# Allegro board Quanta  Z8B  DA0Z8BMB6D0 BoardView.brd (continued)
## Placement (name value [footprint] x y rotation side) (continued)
R522  0_6  [RC0603]  162.51 92.5 270 top
R523  *0_4  [RC0402]  175.56 103.32 270 bottom
R524  *short_4  [SHORT0402]  85.55 103.12 270 bottom
R525  *short_6  [SHORT0603]  179 102.94 0 bottom
R526  150/f_4  [RC0402]  12.88 102.79 270 bottom
R527  *0_8_s  [SHORT0805]  31.7 102.23 270 bottom
R528  0.002/f_2512  [RC2512]  141.99 101.72 0 bottom
R529  *iv@10k_4  [RC0402]  177.5 101.67 180 bottom
R531  *short_4  [SHORT0402]  148.67 101.49 0 bottom
R532  *short_4  [SHORT0402]  37.43 101.42 0 bottom
R533  130/f_4  [RC0402]  86.85 100.88 90 bottom
R534  *short_4  [SHORT0402]  85.7 100.81 270 bottom
R535  150/f_4  [RC0402]  12.88 100.75 90 bottom
R536  10k_4  [RC0402]  177.73 100.3 180 bottom
R537  2.2_6  [RC0603]  34.12 100.2 0 bottom
R538  *0_4  [RC0402]  175.49 100.02 180 bottom
R539  *short_4  [SHORT0402]  88.9 99.15 0 bottom
R540  1k_4  [RC0402]  85.23 99.14 0 bottom
R541  *330k_4  [RC0402]  176.76 98.62 0 bottom
R542  330k_4  [RC0402]  178.82 98.62 180 bottom
R543  150/f_4  [RC0402]  11.86 98.6 270 bottom
R544  *0_4  [RC0402]  86.65 97.96 0 bottom
R545  *short_4  [SHORT0402]  88.92 97.93 0 bottom
R546  *short_4  [SHORT0402]  86.65 96.73 180 bottom
R547  *0_4  [RC0402]  88.92 96.73 180 bottom
R548  *short_4  [SHORT0402]  179.48 96.39 0 bottom
R549  100k_4  [RC0402]  190.96 95.93 90 bottom
R550  *short_4  [SHORT0402]  88.91 95.52 0 bottom
R551  10k_4  [RC0402]  186.26 94.54 90 bottom
R552  *0_4  [RC0402]  88.91 94.32 180 bottom
R553  *short_4  [SHORT0402]  85.65 94.31 180 bottom
R554  10m_4  [RC0402]  178.28 94.3 90 bottom
R555  10k_4  [RC0402]  183.3 94.27 90 bottom
R556  10k_4  [RC0402]  184.86 94.25 90 bottom
R557  *short_4  [SHORT0402]  88.91 93.13 0 bottom
R558  *0_4  [RC0402]  85.65 93.12 0 bottom
R559  10k_4  [RC0402]  185.4 92.5 180 bottom
R560  0_12  [RC1206]  23.07 92.35 90 bottom
R561  *short_4  [SHORT0402]  88.92 91.93 180 bottom
R562  *short_6  [SHORT0603]  185.07 90.75 180 bottom
R563  *short_4  [SHORT0402]  88.93 90.74 180 bottom
R564  1m_8  [RC0805]  27.21 90.52 180 bottom
R565  10k_4  [RC0402]  149.9 90.41 270 bottom
R566  10k_4  [RC0402]  148.77 90.39 270 bottom
R567  *short_4  [SHORT0402]  85.83 90.08 90 bottom
R568  10k_4  [RC0402]  158.02 89.94 90 bottom
R569  *short_4  [SHORT0402]  156.95 89.94 90 bottom
R570  *1k_4  [RC0402]  152.56 89.82 90 bottom
R571  *short_4  [SHORT0402]  153.63 89.69 270 bottom
R572  *1k_4  [RC0402]  154.85 89.82 90 bottom
R573  10k_4  [RC0402]  161.7 89.82 270 bottom
R574  51_4  [RC0402]  162.85 89.82 90 bottom
R575  10k_4  [RC0402]  163.99 89.82 270 bottom
R576  10k_4  [RC0402]  165.13 89.82 270 bottom
R577  *short_4  [SHORT0402]  166.28 89.82 270 bottom
R578  10k_4  [RC0402]  167.42 89.82 270 bottom
R579  1k_4  [RC0402]  170.98 89.82 90 bottom
R580  10k_4  [RC0402]  172.12 89.82 90 bottom
R581  *short_4  [SHORT0402]  173.26 89.82 90 bottom
R582  *short_4  [SHORT0402]  175.55 89.82 270 bottom
R583  *short_4  [SHORT0402]  177.88 89.72 270 bottom
R584  10k_4  [RC0402]  174.4 89.69 90 bottom
R585  10k_4  [RC0402]  168.84 89.59 90 bottom
R586  *short_4  [SHORT0402]  169.93 89.58 270 bottom
R587  *short_4  [SHORT0402]  88.91 89.46 0 bottom
R588  *short_4  [SHORT0402]  176.71 88.46 270 bottom
R589  1k_4  [RC0402]  181.56 87.22 270 bottom
R590  10k_4  [RC0402]  163.98 87.32 90 bottom
R591  *short_4  [SHORT0402]  168.02 87.3 270 bottom
R592  *short_4  [SHORT0402]  148.75 87.28 90 bottom
R593  *0_4  [RC0402]  149.89 87.28 90 bottom
R594  390_4  [RC0402]  151.04 87.28 90 bottom
R595  *short_4  [SHORT0402]  153.22 87.28 90 bottom
R596  *1k_4  [RC0402]  154.47 87.28 90 bottom
R597  *short_4  [SHORT0402]  155.51 87.28 90 bottom
R598  10k_4  [RC0402]  156.65 87.28 90 bottom
R599  ev@10k_4  [RC0402]  159.04 87.28 270 bottom
R600  10k_4  [RC0402]  160.56 87.28 270 bottom
R601  *1k_4  [RC0402]  165.13 87.28 90 bottom
R602  *short_4  [SHORT0402]  166.28 87.28 270 bottom
R603  *short_4  [SHORT0402]  170.98 87.28 270 bottom
R604  *short_4  [SHORT0402]  172.12 87.28 90 bottom
R605  *short_4  [SHORT0402]  173.26 87.28 270 bottom
R606  10k_4  [RC0402]  174.4 87.28 90 bottom
R607  *short_4  [SHORT0402]  169.13 87.25 270 bottom
R608  *iv@100k_4  [RC0402]  157.76 87.22 270 bottom
R609  *short_4  [SHORT0402]  161.72 86.98 90 bottom
R610  *short_4  [SHORT0402]  152.07 86.28 270 bottom
R611  *short_4  [SHORT0402]  160.15 85.2 90 bottom
R612  *short_4  [SHORT0402]  162.95 85.16 90 bottom
R613  *short_4  [SHORT0402]  168.07 85.15 270 bottom
R614  10k_4  [RC0402]  166.21 85.14 270 bottom
R615  *short_4  [SHORT0402]  164.03 85.13 90 bottom
R616  *short_4  [SHORT0402]  148.75 85.12 270 bottom
R617  *short_4  [SHORT0402]  155.61 85.12 90 bottom
R618  1k_4  [RC0402]  156.75 85.12 90 bottom
R619  *short_4  [SHORT0402]  157.82 85.12 90 bottom
R620  *1k_4  [RC0402]  159.04 85.12 90 bottom
R621  *short_4  [SHORT0402]  165.13 85.12 90 bottom
R622  10k_4  [RC0402]  151.03 85.1 270 bottom
R623  *short_4  [SHORT0402]  149.9 85.1 270 bottom
R624  *0_4  [RC0402]  172.82 85.04 270 bottom
R625  *short_4  [SHORT0402]  173.97 85.04 90 bottom
R626  1/f_4  [RC0402]  30.89 84.93 0 bottom
R627  *short_4  [SHORT0402]  170.1 84.68 270 bottom
R628  10k_4  [RC0402]  154.35 84.1 90 bottom
R629  1/f_4  [RC0402]  30.89 83.79 0 bottom
R630  *short_4  [SHORT0402]  157.21 83.09 270 bottom
R631  10k_4  [RC0402]  158.28 83.09 270 bottom
R632  *short_4  [SHORT0402]  159.42 83.09 270 bottom
R633  210/f_4  [RC0402]  160.56 83.09 270 bottom
R634  100/f_4  [RC0402]  161.7 83.09 90 bottom
R635  100/f_4  [RC0402]  162.96 83.08 90 bottom
R636  10k_4  [RC0402]  165.89 82.29 270 bottom
R637  *0_4  [RC0402]  154.34 81.93 90 bottom
R638  *short_4  [SHORT0402]  167.01 81.91 90 bottom
R639  1k_4  [RC0402]  172.65 81.86 270 bottom
R640  100/f_4  [RC0402]  164.21 80.94 90 bottom
R641  *short_4  [SHORT0402]  163.01 80.71 90 bottom
R642  210/f_4  [RC0402]  165.33 80.26 270 bottom
R643  1/f_4  [RC0402]  30.31 79.94 0 bottom
R644  1k_4  [RC0402]  149.11 79.69 270 bottom
R645  15_4  [RC0402]  145.42 79.67 90 bottom
R646  15_4  [RC0402]  142.83 79.67 90 bottom
R647  15_4  [RC0402]  144.1 79.67 90 bottom
R648  15_4  [RC0402]  146.59 79.66 90 bottom
R649  15_4  [RC0402]  147.86 79.66 270 bottom
R650  1/f_4  [RC0402]  30.31 78.67 0 bottom
R651  1/f_4  [RC0402]  30.31 77.38 0 bottom
R652  *short_6  [SHORT0603]  150.73 77.18 90 bottom
R653  1/f_4  [RC0402]  30.31 76.11 0 bottom
R654  1/f_4  [RC0402]  30.33 72.33 0 bottom
R655  1/f_4  [RC0402]  30.33 71.06 0 bottom
R656  *short_4  [SHORT0402]  181.72 68.81 270 bottom
R657  1k_4  [RC0402]  144.33 67.22 90 bottom
R658  15_4  [RC0402]  145.6 67.22 270 bottom
R659  15_4  [RC0402]  146.87 67.22 270 bottom
R660  15_4  [RC0402]  148.14 67.22 270 bottom
R661  15_4  [RC0402]  149.41 67.22 270 bottom
R662  *kbl@0_4  [RC0402]  151.97 66.57 270 bottom
R663  15_4  [RC0402]  145.26 65.21 0 bottom
R664  *kbl@10k_4  [RC0402]  155.63 64.89 180 bottom
R665  *short_4  [SHORT0402]  186.56 63.66 90 bottom
R666  *0_6  [RC0603]  169.59 62.93 90 bottom
R667  *short_4  [SHORT0402]  181.91 62.8 90 bottom
R668  *short_4  [SHORT0402]  183.05 62.8 90 bottom
R669  *short_4  [SHORT0402]  184.19 62.8 90 bottom
R670  *short_4  [SHORT0402]  185.34 62.8 90 bottom
R671  *0_4  [RC0402]  171.87 62.68 270 bottom
R672  *0_4  [RC0402]  173.14 62.68 270 bottom
R673  0_4  [RC0402]  177.08 62.68 270 bottom
R674  470_4  [RC0402]  15.01 56.84 0 bottom
R675  *120/f_4  [RC0402]  13.49 56.2 270 bottom
R676  470_4  [RC0402]  15.01 55.57 0 bottom
R677  4.7k_4  [RC0402]  155.11 53.87 90 bottom
R678  4.7k_4  [RC0402]  155.09 51.58 270 bottom
R679  *0_4  [RC0402]  186.35 48.96 180 bottom
R680  4.7k_4  [RC0402]  188.64 48.96 0 bottom
R681  100k_4  [RC0402]  174.29 48.45 0 bottom
R682  *short_4  [SHORT0402]  163.45 47.9 90 bottom
R683  *0_4  [RC0402]  165.19 47.36 90 bottom
R684  *0_4  [RC0402]  166.34 47.36 90 bottom
R685  *short_8  [SHORT0805]  168.8 48.52 180 bottom
R686  *short_4  [SHORT0402]  180.89 47.06 90 bottom
R687  *short_4  [SHORT0402]  182.03 47.06 90 bottom
R688  4.7k_4  [RC0402]  183.58 47.06 90 bottom
R689  *0_4  [RC0402]  186.37 45.21 0 bottom
R690  *short_6  [SHORT0603]  33.24 34.71 0 bottom
R691  4.7k_4  [RC0402]  25.81 34.61 270 bottom
R692  *0_4  [RC0402]  29.24 34.61 270 bottom
R693  *short_4  [SHORT0402]  30.25 34.61 90 bottom
R694  10k_4  [RC0402]  19.28 33.57 0 bottom
R695  100k_4  [RC0402]  21.77 30.17 270 bottom
R696  *10k/f_4  [RC0402]  38.13 26.49 90 bottom
R697  *29.4k/f_4  [RC0402]  38.13 24.2 270 bottom
R698  *short_4  [SHORT0402]  29.62 19.25 90 bottom
R699  90.9_4  [RC0402]  38.38 19.12 270 bottom
R700  90.9_4  [RC0402]  35.97 18.99 270 bottom
R701  90.9_4  [RC0402]  40.79 18.99 270 bottom
R702  90.9_4  [RC0402]  19.2 18.23 270 bottom
R703  90.9_4  [RC0402]  20.47 18.23 270 bottom
R704  90.9_4  [RC0402]  21.74 18.23 270 bottom
R705  90.9_4  [RC0402]  23.4 18.23 270 bottom
R706  90.9_4  [RC0402]  26.32 18.23 270 bottom
R707  *1k_4  [RC0402]  28.5 18.13 90 bottom
R708  *100k_4  [RC0402]  31.5 17.72 180 bottom
R709  *short_6  [SHORT0603]  38.64 14.8 180 bottom
R710  *short_4  [SHORT0402]  36.86 13.53 180 bottom
R711  *short_4  [SHORT0402]  36.86 12.52 180 bottom
R712  *short_4  [SHORT0402]  170.87 11.99 180 bottom
R713  10k_4  [RC0402]  173.15 11.99 0 bottom
R714  *0_4  [RC0402]  175.41 12.08 0 bottom
R715  *short_4  [SHORT0402]  170.87 10.59 180 bottom
R716  10k_4  [RC0402]  173.15 10.59 0 bottom
R717  *0_4  [RC0402]  174.68 9.67 270 bottom
R718  *1m_4  [RC0402]  66.96 9.59 270 bottom
R719  *1m_4  [RC0402]  68.23 9.59 270 bottom
R720  *short_4  [SHORT0402]  173.15 9.39 0 bottom
R721  *1m_4  [RC0402]  63.91 8.83 270 bottom
R722  *1m_4  [RC0402]  65.18 8.83 270 bottom
R723  680/f_4  [RC0402]  66.96 7.31 90 bottom
R724  2k/f_4  [RC0402]  68.23 7.31 90 bottom
R725  680/f_4  [RC0402]  63.91 6.67 90 bottom
R726  2k/f_4  [RC0402]  65.18 6.67 90 bottom
R727  *short_4  [SHORT0402]  103.36 5.15 0 bottom
R728  2.2k_4  [RC0402]  24.29 111.83 90 top
R729  2.2k_4  [RC0402]  18.55 113.36 90 top
R730  2.2k_4  [RC0402]  22 109.67 90 top
R731  2.2k_4  [RC0402]  20.98 109.67 90 top
R732  ev@10k_4  [RC0402]  161.07 179.27 180 top
R733  ev@10k_4  [RC0402]  168.3 148.79 90 bottom
R734  *short_4  [SHORT0402]  135.16 116.66 180 bottom
R735  *short_4  [SHORT0402]  135.16 117.67 180 bottom
R736  *short_4  [SHORT0402]  135.16 115.64 180 bottom
R737  *short_4  [SHORT0402]  135.16 114.62 180 bottom
R738  *short_4  [SHORT0402]  135.16 112.59 180 bottom
R739  *short_4  [SHORT0402]  135.16 113.61 180 bottom
R740  *10k_4  [RC0402]  183.01 173.07 270 top
R741  *1k_4  [RC0402]  176.74 175.94 180 top
R742  *1k_4  [RC0402]  173.18 172.87 90 top
R743  ev@0_4  [RC0402]  171.23 162.43 90 bottom
R744  *short_4  [SHORT0402]  149.41 122.87 270 bottom
R745  *short_4  [SHORT0402]  148.4 122.87 270 bottom
R746  *short_4  [SHORT0402]  175.7 10.44 270 bottom
RP1  10k_10p8r_6  [10P8R]  167.93 86.14 90 top
RP2  *10k_10p8r  [10P8R]  177.57 20.01 180 top
RP7  10k_10p8r_6  [10P8R]  182.3 100.53 0 bottom
RV1  *ega_4  [RC0402]  17.05 39.06 180 bottom
RV2  *ega_4  [RC0402]  17.05 37.92 180 bottom
RV3  *ega_4  [RC0402]  17.07 36.75 180 bottom
RV4  *ega_4  [RC0402]  17.07 35.6 180 bottom
RV5  *ega_4  [RC0402]  17.05 34.38 180 bottom
RV6  *ega_4  [RC0402]  17.05 33.24 180 bottom
SW1  *power switch  [SW-TC901-AA1G-A160T-6P]  161.32 68.9 270 top
T1  *pad  [TP2650]  25.63 25.61 0 top
T2  *pad  [TP2650]  25.74 24.23 0 top
TP1  *  [TP2650]  106.76 189.48 0 top
TP2  *  [TP2650]  108.06 189.45 0 top
TP3  *  [TP2650]  108.56 188.11 0 top
TP4  *  [TP2650]  107.09 187.7 0 top
TP5  *  [TP2050]  146.44 169.97 90 top
TP6  *  [TP2675]  150.14 166.31 90 top
TP7  *  [TP2675]  151.16 164.68 90 top
TP8  *  [TP2050]  149.75 163.36 90 top
TP9  *  [TP2650]  134.24 161.51 90 top
TP10  *  [TP2650]  139.65 158.78 90 top
TP11  *  [TP2650]  187.58 150.13 0 top
TP12  *  [TP2675]  118.47 126 270 top
TP13  *  [TP2650]  97.3 124.09 0 top
TP14  *  [TP2675]  118.44 124.05 270 top
TP15  *  [TP2675]  94.57 122.14 270 top
TP16  *  [TP2675]  94.26 120.21 270 top
TP17  *  [TP2650]  98.78 118.43 0 top
TP18  *  [TP2650]  97.01 117.42 0 top
TP19  *  [TP2650]  171.73 115.51 0 top
TP20  *  [TP2650]  93.23 114.57 0 top
TP21  *  [TP2650]  170.72 113.69 0 top
TP22  *  [TP2675]  93.2 112.87 90 top
TP23  *  [TP2675]  91.09 112.85 90 top
TP24  *  [TP2675]  94.85 111.19 90 top
TP25  *  [TP2650]  169.22 110.84 0 top
TP26  *  [TP2675]  90.99 110.86 90 top
TP27  *  [TP2650]  131.22 110.76 0 top
TP28  *  [TP2675]  92.97 110.56 90 top
TP29  *  [TP2675]  90.86 108.91 270 top
TP30  *  [TP2650]  87.18 108.09 0 top
TP31  *  [TP2650]  85.81 108.05 0 top
TP32  *  [TP2650]  24.01 102.61 180 top
TP33  *  [TP2650]  22.03 102.35 90 top
TP34  *  [TP2650]  86.34 102.05 0 top
TP35  *  [TP2675]  171.23 101.8 0 top
TP36  *  [TP2650]  22 100.65 180 top
TP37  *  [TP2650]  85.17 100.58 0 top
TP38  *  [TP2650]  8.04 100.48 0 top
TP39  *  [TP2650]  84.42 98.77 0 top
TP40  *  [TP2675]  147.07 98.44 0 top
TP41  *  [TP2650]  85.75 98.42 0 top
TP42  *  [TP2675]  149.7 98.32 0 top
TP43  *  [TP2675]  147.07 96.49 0 top
TP44  *  [TP2675]  149.76 96.41 0 top
TP45  *  [TP2675]  159.67 96.54 0 top
TP46  *  [TP2675]  162.69 95.6 0 top
TP47  *  [TP2675]  165.56 95.29 0 top
TP48  *  [TP2675]  155.73 94.68 0 top
TP49  *  [TP2675]  160.79 94.96 0 top
TP50  *  [TP2675]  159.76 98.56 0 top
TP51  *  [TP2675]  170.79 92.75 0 top
TP52  *  [TP2675]  158.68 93.8 0 top
TP53  *  [TP2675]  154.78 91.49 0 top
TP54  *  [TP2675]  103 90.37 270 top
TP55  *  [TP2675]  170.16 89.99 0 top
TP56  *  [TP2675]  106.38 89.5 270 top
TP57  *  [TP2675]  162.98 87.02 0 top
TP58  *  [TP2650]  161.73 85.98 0 top
TP59  *  [TP2675]  185.45 84.75 0 top
TP60  *  [TP2650]  159.03 83.37 0 top
TP61  *  [TP2675]  179.9 82.51 0 top
TP62  *  [TP2650]  126.09 82.03 0 top
TP63  *  [TP2675]  180.04 80.49 0 top
TP64  *  [TP2650]  60.63 76.24 0 top
TP65  *  [TP2650]  166.32 70.79 0 top
TP66  *  [TP2650]  166.27 69.28 0 top
TP67  *  [TP2650]  156.49 67.13 0 top
TP68  *  [TP2650]  77.39 66.32 0 top
TP69  *  [TP2650]  178.95 65.47 0 top
TP70  *  [TP2650]  186 57.11 0 top
TP71  *  [TP2650]  140.21 54.27 0 top
TP72  *  [TP2650]  166.65 45.23 0 top
TP73  *  [TP2650]  34.26 33.07 90 top
TP74  *  [TP2650]  164.55 17.87 0 top
TP75  *  [TP2650]  118.01 11.25 0 top
TP76  *  [TP2650]  48.19 7.69 0 top
TP77  *  [TP2650]  177.68 174.03 180 bottom
TP78  *  [TP2650]  136.83 173.12 270 bottom
TP79  *  [TP2675]  163.5 149.04 270 bottom
TP80  *  [TP2675]  165.23 147.74 270 bottom
TP81  *  [TP2675]  150.63 141.57 270 bottom
TP82  *  [TP2675]  154.54 141.12 270 bottom
TP83  *  [TP2650]  93.63 123.03 180 bottom
TP84  *  [TP2650]  93.7 121.74 180 bottom
TP85  *  [TP2650]  148.64 120.44 180 bottom
TP86  *  [TP2650]  147.38 120.37 180 bottom
TP87  *  [TP2650]  170.18 117.59 180 bottom
TP88  *  [TP2650]  86.01 114.12 180 bottom
TP89  *  [TP2650]  84.71 114.06 180 bottom
TP90  *  [TP2650]  89.44 113.73 180 bottom
TP91  *  [TP2650]  85.32 111.83 180 bottom
TP92  *  [TP2650]  86.67 111.75 180 bottom
TP93  *  [TP2650]  87.94 109.47 180 bottom
TP94  *  [TP2650]  89.41 109.42 180 bottom
TP95  *  [TP2650]  85.17 109.04 180 bottom
TP96  *  [TP2650]  85.48 106.98 180 bottom
TP97  *  [TP2650]  87.2 106.5 180 bottom
TP98  *  [TP2675]  175.73 106.11 180 bottom
TP99  *  [TP2650]  86.08 105.86 180 bottom
TP100  *  [TP2650]  87.33 105.02 180 bottom
TP101  *  [TP2650]  139.27 105.02 180 bottom
TP102  *  [TP2050]  174.6 103.27 180 bottom
TP103  *  [TP2675]  179.73 101.85 180 bottom
TP104  *  [TP2650]  39.45 101.57 180 bottom
TP105  *  [TP2650]  87.07 99.07 180 bottom
TP106  *  [TP2675]  175.34 98.72 180 bottom
TP107  *  [TP2675]  149.05 98.37 180 bottom
TP108  *  [TP2675]  147.12 98.34 270 bottom
TP109  *  [TP2650]  83.77 98.19 180 bottom
TP110  *  [TP2650]  85.06 97.95 180 bottom
TP111  *  [TP2675]  146.59 96.44 270 bottom
TP112  *  [TP2675]  148.77 96.44 180 bottom
TP113  *  [TP2650]  85.07 95.54 180 bottom
TP114  *  [TP2650]  86.34 95.53 180 bottom
TP115  *  [TP2675]  149.03 94.51 0 bottom
TP116  *  [TP2675]  147.1 94.43 0 bottom
TP117  *  [TP2650]  87.25 93.77 180 bottom
TP118  *  [TP2675]  145.6 93.16 180 bottom
TP119  *  [TP2675]  147.38 92.3 180 bottom
TP120  *  [TP2650]  84.58 91.97 180 bottom
TP121  *  [TP2650]  87.2 91.89 180 bottom
TP122  *  [TP2650]  85.91 91.88 180 bottom
TP123  *  [TP2675]  175.47 91.36 90 bottom
TP124  *  [TP2650]  153.6 91.31 180 bottom
TP125  *  [TP2650]  155.38 91.26 180 bottom
TP126  *  [TP2650]  87.13 90.6 180 bottom
TP127  *  [TP2675]  179.38 90.21 180 bottom
TP128  *  [TP2650]  155.97 89.24 180 bottom
TP129  *  [TP2650]  87.17 89.2 180 bottom
TP130  *  [TP2675]  177.86 88.13 180 bottom
TP131  *  [TP2650]  170.05 87.91 180 bottom
TP132  *  [TP2650]  152.14 87.8 180 bottom
TP133  *  [TP2675]  175.5 87.35 90 bottom
TP134  *  [TP2650]  167.19 85.85 180 bottom
TP135  *  [TP2650]  154.54 85.8 180 bottom
TP136  *  [TP2650]  153.06 85.49 180 bottom
TP137  *  [TP2650]  161.24 85 180 bottom
TP138  *  [TP2650]  167.19 84.58 180 bottom
TP139  *  [TP2650]  152.15 84.53 180 bottom
TP140  *  [TP2675]  171.68 83.89 90 bottom
TP141  *  [TP2650]  165.13 83.69 180 bottom
TP142  *  [TP2650]  168.12 83.67 180 bottom
TP143  *  [TP2675]  173.64 83.48 90 bottom
TP144  *  [TP2650]  163.89 83.43 180 bottom
TP145  *  [TP2650]  166.88 83.34 180 bottom
TP146  *  [TP2650]  156.12 83.31 180 bottom
TP147  *  [TP2650]  170.1 83.25 180 bottom
TP148  *  [TP2650]  168.92 82.65 180 bottom
TP149  *  [TP2650]  164.7 82.42 180 bottom
TP150  *  [TP2650]  156.52 81.53 180 bottom
TP151  *  [TP2650]  159.43 81.38 180 bottom
TP152  *  [TP2650]  169.17 81.3 180 bottom
TP153  *  [TP2650]  171.73 80.61 180 bottom
TP154  *  [TP2650]  161.92 80.32 180 bottom
TP155  *  [TP2650]  54.54 77.31 180 bottom
TP156  *  [TP2650]  170.63 63.16 180 bottom
TP157  *  [TP2650]  16.62 61.26 180 bottom
TP158  *  [TP2650]  153.66 56.12 180 bottom
TP159  *  [TP2650]  46.26 55.47 180 bottom
TP160  *  [TP2650]  155.12 55.47 180 bottom
TP161  *  [TP2650]  154.15 52.24 180 bottom
TP162  *  [TP2650]  154.13 50.89 180 bottom
TP163  *  [TP2650]  165.2 49.06 180 bottom
TP164  *  [TP2650]  145.67 47.21 180 bottom
TP165  *pad  [TP2650]  28.86 16.45 270 bottom
TP166  *pad  [TP2650]  34.32 10.53 270 bottom
TP167  *  [TP2650]  170.34 9.42 180 bottom
TP168  *  [TP2650]  171.68 9.42 180 bottom
TP169  *pad  [TP2650]  30.08 9.31 270 bottom
TP170  *pad  [TP2650]  31.58 9.31 270 bottom
TP171  *pad  [TP2650]  32.95 9.26 270 bottom
TP172  *pad  [TP2650]  34.35 9.24 270 bottom
TP173  *pad  [TP2650]  27.82 8.88 270 bottom
TP174  *pad  [TP2650]  30.13 8.04 270 bottom
TP175  *pad  [TP2650]  31.4 8.04 270 bottom
TP176  *  [TP2650]  74.83 6.39 180 bottom
TP177  *  [TP2675]  146.74 65.25 0 top
TP178  *  [TP2675]  144.96 81.32 180 bottom
TP179  *  [TP2675]  145.37 77.69 0 top
TP180  *  [TP2675]  144.86 65.6 0 top
TP181  *  [TP2675]  182.5 87.95 180 bottom
U1  *g780p81u  [MSOP8-4_9-65]  166.78 177.74 90 top
U2  g5243at11u  [SOT23-2_8-95-6P]  109.07 174.36 270 top
U3  *74aup1g07gw  [SOT353-1-2_125-65-5P]  179.94 170.62 0 top
U5  74lvc1g07gw  [SOT353-2_1-65-5P-1_1H]  84.41 103.12 270 top
U6  *rclamp0524p  [SLP10-2_5X1-5-10P]  9.76 100.93 90 top
U7  rtl8111gs-cg  [QFN32-4X4-4-33P-0_9H]  27.92 98.34 0 top
U8  tc7sh08fu  [SSOP5-P-A-TOSHIBA-B]  183.4 82.47 90 top
U9  *cm1293a-04so  [TSOP6-2_8-95]  30.99 82.03 180 top
U10  *cm1293a-04so  [TSOP6-2_8-95]  32.26 76.24 270 top
U11  tpm@npct650aa0wx_tssop28  [TSSOP28-6_4-65-SLB9635TT]  182.42 71.06 180 top
U12  *74ahc1g09gw  [SOT353-1-2_125-65-5P]  77.04 70.22 270 top
U13  it8587e/fx  [LQFP128-16X16-4-1_6H]  175.43 54.93 270 top
U15  alc283  [QFN48-6X6-4-49P-ALC280]  30 29.03 180 top
U16  *gs@lis3dhtr  [SENSOR-3X3-5-16P-SMT]  113.18 12.9 0 top
U17  d-mic  [MIC-MP45DT02TR-6P]  104.5 3.35 180 top
U18  *ev@sn74ahc1g32dckr  [SSOP5-P-A-TOSHIBA-B]  169.24 162.43 90 bottom
U19  ev@n15s  [BGA595-NVIDIA-N13P-GV2-S-A2]  146.69 158.34 180 bottom
U20  evg@mc74vhc1g08dft2g  [SSOP5-P-A-TOSHIBA-B]  168.71 153 270 bottom
U21  *ev@mc74vhc1g08dft2g  [SSOP5-P-A-TOSHIBA-B]  166 152.98 270 bottom
U22  m74vhc1gt125df2g  [SSOP5-P-A-TOSHIBA-B]  14.38 107.64 270 bottom
U23  *rclamp0524p  [SLP10-2_5X1-5-10P]  9.7 106.72 90 bottom
U24  lpt_pch_m_eds/bga  [BGA695-INTEL-LYNX-POINT]  162.2 104.45 270 bottom
U25  m74vhc1gt125df2g  [SSOP5-P-A-TOSHIBA-B]  14.76 103.45 270 bottom
U26  g991p11u  [SOIC8-6-1_27]  58.7 101.87 270 bottom
U27  hsw_rpga_eds_pga  [PZ94726-3641-41H-SOCKET]  111.9 99.69 180 bottom
U28  tc7sh08fu  [SSOP5-P-A-TOSHIBA-B]  192.18 99.51 0 bottom
U29  ns692417  [TRF-9_4-1_27-24P]  23.37 78.02 270 bottom
U30  w25q64fvssiq  [SOIC8-7_9-1_27]  147.22 73.48 180 bottom
U31  *g923-330t1uf  [SOT23-5]  40.54 25.47 0 bottom
U32  qfn24-3.3v  [QFN24-4X4-5-25P-1H]  30.89 12.69 180 bottom
U33  g524b2t11u  [SOT23-5]  23.4 43.76 180 top
VC1  *tvm0g5r5m261r_4  [CC0402]  27.08 43 270 top
VC2  *tvm0g5r5m261r_4  [CC0402]  17.94 45.15 90 bottom
VRAM1  ev@vram _ddr3_hynix_256mx16  [FBGA96-AMD-23EY4187MA11]  121.15 168.34 0 top
VRAM2  ev@vram _ddr3_hynix_256mx16  [FBGA96-AMD-23EY4187MA11]  121.15 148.05 180 top
VRAM3  ev@vram _ddr3_hynix_256mx16  [FBGA96-AMD-23EY4187MA11]  121.15 168.34 180 bottom
VRAM4  ev@vram _ddr3_hynix_256mx16  [FBGA96-AMD-23EY4187MA11]  121.15 148.05 0 bottom
Y1  25mhz +-30ppm  [XTL-3_2X2_5-2_2X1_7]  21.01 97.61 90 top
Y2  ev@27mhz  [XTL-3_2X2_5-2_2X1_6]  153.22 176.9 180 bottom
Y3  25mhz +-30ppm  [XTL-3_2X2_5-2_2X1_7]  157.51 120.43 0 bottom
Y4  32.768khz  [XTL-3_2X1_5-2_5-0_8H]  179.91 93.67 270 bottom

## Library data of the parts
BT1 = ML1220-SMT
C1 C2 C4-C10 C12-C15 C17-C25 C27 C29 C34 C35 C40-C42 C47-C49 C51 C53 C55 C58 C64 C70-C75 C80 C82-C98 C103-C114 C116 C120-C127 C129-C137 C140-C157 C160-C169 C175 C177-C183 C189 C190 C196 C198 C204 C211 C213 C215-C230 C232 C235-C240 C242-C245 C247-C250 C257 C259 C260 C263 C265-C267 C270-C274 C278 C284 C285 C288-C292 C296 C300-C338 C340-C357 C359-C361 C363-C365 C367 C369-C376 C379 C387 C389 C391-C405 C407 C409-C427 C429 C430 C432 C433 C435-C438 C445-C447 C449 C452 C457-C459 C462 C463 C469-C475 C481-C485 C487 C488 C494-C499 C501-C504 C506-C508 C510-C515 C517-C523 C525-C534 C536 C538-C542 C544 C545 C547-C549 C551 C553-C558 C560-C568 C570 C716-C754 PC13 PC20 PC21 PC23-PC28 PC33 PC49 PC52 PC59 PC61 PC62 PC68-PC70 PC72 PC77 PC78 PC80 PC86-PC94 PC98 PC101-PC105 PC112 PC113 PC115 PC116 PC119 PC121-PC124 PC126 PC130 PC131 PC136 PC139 PC140 PC142 PC145-PC148 PC154-PC158 PC161 PC163 PC166 PC168 VC1 VC2 = CC0402
C3 C26 C28 C30 C31 C33 C36-C39 C43-C46 C50 C52 C54 C56 C57 C59-C63 C65-C69 C76-C79 C81 C99-C102 C138 C205 C212 C214 C233 C234 C241 C246 C252-C255 C258 C261 C262 C264 C268 C269 C275 C276 C279-C282 C286 C293-C295 C297 C298 C339 C366 C368 C377 C378 C380 C382-C386 C406 C434 C444 C448 C450 C460 C461 C509 C516 C524 C535 C537 C546 C550 C552 C559 C715 PC1-PC12 PC15 PC16 PC18 PC22 PC31 PC32 PC34 PC35 PC37 PC38 PC40 PC41 PC43-PC48 PC50 PC53 PC54 PC56-PC58 PC60 PC64 PC65 PC67 PC71 PC76 PC79 PC84 PC85 PC95-PC97 PC99 PC100 PC106-PC108 PC114 PC120 PC125 PC127 PC135 PC138 PC141 PC149 PC151 PC152 PC160 PC167 PC169 PC170 = CC0603
C11 C16 C32 C115 C117 C118 C128 C139 C158 C159 C170-C174 C176 C184-C188 C191-C195 C197 C199-C203 C206-C210 C231 C251 C256 C277 C299 C362 C388 C390 C408 C431 C439-C443 C451 C453-C456 C464-C468 C476-C480 C486 C489-C493 C543 PC14 PC17 PC19 PC30 PC36 PC51 PC63 PC73 PC74 PC82 PC83 PC109 PC110 PC117 PC128 PC129 PC132 PC137 PC143 PC144 PC150 PC159 PC164 PC165 = CC0805
C287 C358 C428 C569 = CC3528
C381 L6 L16 L19 L22 L23 L29 L30 L32 L33 PR22 PR48 PR49 PR51 PR53 PR61 PR64-PR66 PR73 PR79 PR82 PR83 PR88 PR94 PR105 PR126 PR144 PR152 PR155 PR160 PR168 PR175 PR177 PR183 PR190 PR209 PR210 PR213-PR216 R5 R72 R136 R139 R151 R181 R225 R263 R267-R269 R272 R285 R295 R313 R322 R337 R365 R522 R537 R666 = RC0603
C500 = CC1808
C505 = ECAP6D3S
CN1 = SDCARD-5-251301001000-6-11P-SMT
CN2 = GS12401-1011-40P-R-NH-SMT
CN3 = HS8803F-3P-L
CN4 CN8 = 50503-0040N-V01-4P-L
CN5 = DSUB-070546FR015S265ZR-15P-V
CN6 = SATA-C185Q2-11311-L-13P-R
CN7 = RJ45-C100JH-10805-L-8P
CN9 = HDMI-2HE1638-000111F-19P
CN10 = MIPCI-800055FB052GX00PL-52P-SMT
CN11 = HDD-193204-1-22P-R
CN12 = USB-C19083-90905-L-9P
CN13 = 51553-01041-001-10P-L
CN14 = 88502-260N-26P-L-SMT
CN15 = AUDIO-313301-1-6P
CN16 = 196479-06041-3-6P-L
CN17 = 50501-02401-001-24P-L
CN18 = 196297-06021-3-6P-L
CN19 = 50273-0040L-001-4P-L
CP1-CP6 = 8P4R
D1 D3 D4 D6-D10 D12-D15 D18 D23 PD3 PD4 PD7 = DSM
D2 = CC1206
D5 D17 D19 D24 L1-L4 L9 L10 L12 L17 L18 L25-L27 PR3 PR4 PR6 PR8 PR10-PR12 PR14 PR15 PR17 PR25-PR28 PR30 PR31 PR33-PR36 PR38-PR42 PR44 PR47 PR50 PR52 PR54 PR55 PR57 PR58 PR67 PR70-PR72 PR74-PR76 PR80 PR81 PR84-PR87 PR89-PR93 PR95-PR103 PR106-PR114 PR118-PR121 PR127-PR130 PR132-PR134 PR137 PR140-PR143 PR145 PR149 PR150 PR153 PR154 PR156 PR157 PR159 PR161-PR163 PR165 PR169 PR170 PR172-PR174 PR176 PR178 PR179 PR182 PR184 PR189 PR191-PR193 PR195-PR197 PR199 PR201-PR203 PR205 PR207 PR208 PR211 PR212 R1-R4 R7 R9-R16 R18-R25 R27 R29 R30 R32-R43 R45-R49 R51 R52 R56-R58 R60 R63 R65 R68 R69 R71 R77 R79-R86 R89-R94 R96 R100 R102 R104 R106 R107 R109 R111-R113 R115 R119-R122 R124-R126 R130 R131 R133 R135 R137 R138 R140 R146 R147 R153-R162 R164 R166-R180 R182-R189 R193 R194 R196-R199 R201 R203-R210 R214 R216 R217 R219-R224 R226 R227 R229-R232 R235 R238 R240-R244 R246 R247 R249-R255 R258-R262 R264-R266 R270 R271 R275 R276 R278 R279 R281-R284 R287-R291 R293 R294 R296-R298 R300 R302-R308 R310 R311 R314-R321 R323-R326 R329-R334 R338 R340-R343 R345 R346 R348 R351-R353 R355 R357 R358 R360-R362 R366-R370 R376-R378 R383-R411 R413-R415 R418-R424 R426-R433 R435-R454 R457 R459-R461 R463-R467 R469 R471-R476 R479 R480 R483 R490 R492 R494-R498 R501 R503 R505-R510 R513-R515 R517-R521 R523 R526 R529 R533 R535 R536 R538 R540-R544 R547 R549 R551 R552 R554-R556 R558 R559 R565 R566 R568 R570 R572-R576 R578-R580 R584 R585 R589 R590 R593 R594 R596 R598-R601 R606 R608 R614 R618 R620 R622 R624 R626 R628 R629 R631 R633-R637 R639 R640 R642-R651 R653-R655 R657-R664 R671-R681 R683 R684 R688 R689 R691 R692 R694-R697 R699-R708 R713 R714 R716-R719 R721-R726 R728-R733 R740-R743 RV1-RV6 = RC0402
D11 = DSMV
D16 D20 = D-SOD523-1_2X0_8-0_65H
D21 = CC1812
D22 = SOT323_213-2_1-1_3-2N7002W
HOLE1 = HG-TC394BC217D118P2
HOLE2 = HG-TR299X327BC315D118P2
HOLE3 = HG-TC394BC315D118P2
HOLE4 HOLE6 = H-TC236I140BC266D140P2
HOLE5 = H-TC276BC217D118P2
HOLE7 HOLE14 HOLE15 = H-TC315I158BC197D158P2
HOLE8 = HG-C315D189P2
HOLE9 = H-Z8B-1
HOLE10 HOLE11 = SPAD-C236NSNP
HOLE12 HOLE21 HOLE22 = HG-TC276BC315D118P2
HOLE13 = H-C102D102N
HOLE16 = H-ZQ0-1
HOLE17 = H-TC217BC197D140P2
HOLE18 = H-TS315I118BC315D118P2
HOLE19 = O-Z8B-1
HOLE20 HOLE24 = H-C177D177N
HOLE25 = HG-C276D118P2
J2 = SOLDERJUMPER-2
JDIM1 = DDR-DDRSK-20401-TP8D-204P-LDV
JDIM2 = DDR-DS2SK-20401-TP4B-STD-204P
L5 L7 L8 L28 PL5 PL10 PL14 PL15 PR60 PR62 PR63 PR104 PR146-PR148 PR194 PR198 PR204 PR217 PR218 R8 R150 R245 R462 R468 R489 R564 = RC0805
L24 = L3_2X2_5-3_2
LED1 LED2 = LED19-123-Y2ST1D-C30-2T-4P
PC29 PC39 PC42 PC55 PC66 PC75 PC111 PC134 = ECAP6_3X6_1-7_2
PC118 PC133 PC153 PC162 = CC7343
PD1 = POWER-6_5-1_84-3P
PD2 = D-DO-214AC
PD5 PD6 PQ18 PQ29 PQ30 PQ51 Q6 Q9 Q11 Q17 Q28 Q30 Q48 Q50 Q51 = UMT_213-3-1_3
PJ1 = 20288-04XX-4P-L
PJ2 = BAT-C144PL-K08A9-L-8P-L
PL1-PL4 PL7 PL11 PL13 = CHOKE-PCMC063T-3R3MN-SMT
PL6 PL12 = CHOKE-PCMC063T-R82MN-4P-SMT
PL8 PL9 = CHOKE-ETQP4LR36AFM
PQ1 PQ2 PQ36-PQ39 = SO-8FL-5P-OA
PQ3 = IMD
PQ4 PQ8 PQ9 PQ16 PQ17 PQ19-PQ21 PQ27 PQ28 PQ31-PQ35 PQ40 PQ42 PQ44-PQ50 PQ52 PQ53 Q1 Q2 Q4 Q5 Q7 Q10 Q12-Q16 Q18 Q20 Q22-Q27 Q29 Q32-Q43 Q45-Q47 Q49 Q52-Q55 Q57 Q59 Q60 = SOT23_213-3_3-2
PQ5 PQ7 PQ10-PQ15 PQ22-PQ26 PQ43 = WDFN5-3_05X3_05-65
PQ6 Q3 Q8 Q21 Q44 Q56 Q58 = SC70-2_1-65-6P
PQ41 = POWER-5X6-1_27-7P
PR1 PR20 = RC3216
PR2 PR5 PR7 PR18 PR19 PR21 PR23 PR24 PR32 PR37 PR45 PR46 PR68 PR77 PR78 PR115-PR117 PR122 PR123 PR125 PR131 PR135 PR136 PR139 PR164 PR166 PR167 PR171 PR180 PR181 PR185-PR188 PR200 PR206 R26 R28 R31 R44 R50 R59 R66 R87 R88 R97 R103 R110 R118 R123 R132 R141 R148 R152 R163 R165 R191 R192 R195 R200 R202 R211-R213 R215 R218 R228 R234 R239 R256 R257 R273 R274 R277 R280 R299 R301 R328 R336 R339 R344 R347 R349 R350 R354 R356 R359 R363 R364 R375 R379-R382 R412 R425 R434 R455 R456 R458 R470 R478 R481 R484-R487 R491 R499 R500 R502 R504 R511 R516 R524 R531 R532 R534 R539 R545 R546 R548 R550 R553 R557 R561 R563 R567 R569 R571 R577 R581-R583 R586-R588 R591 R592 R595 R597 R602-R605 R607 R609-R613 R615-R617 R619 R621 R623 R625 R627 R630 R632 R638 R641 R656 R665 R667-R670 R682 R686 R687 R693 R698 R710-R712 R715 R720 R727 R734-R739 R744-R746 = SHORT0402
PR9 PR16 PR29 PR43 PR56 PR59 PR69 PR138 PR151 PR158 R6 R55 R67 R70 R73 R74 R76 R78 R95 R98 R99 R108 R114 R116 R127 R129 R143 R144 R149 R286 R292 R309 R312 R335 R371-R374 R416 R417 R493 R525 R562 R652 R690 R709 = SHORT0603
PR13 R105 R117 R128 R233 R236 R237 R248 R482 R560 = RC1206
PR124 R17 R53 R54 R61 R62 R64 R75 R101 R134 R142 R190 R327 R477 R488 R512 R527 R685 = SHORT0805
PU1 = PVQFN20-3_5X3_5-5-25P
PU2 = SOT23-6-2_8-95-6P
PU3 PU5 = QFN20-3X3-4-26P
PU4 PU11 = SON10-3X3-5-16P
PU6 PU12 = SON8-4_5X3_5-5-9P-SMT
PU7 = QFN32-4X4-4-42P-1H
PU8 = QFN16-3X3-5-22P
PU9 U26 = SOIC8-6-1_27
PU10 = QFN20-3X3-4-21P-0_8H
Q19 U9 U10 = TSOP6-2_8-95
Q31 = POWER-3_3X3_3-65-5P-SMT
R145 R528 = RC2512
RP1 RP2 RP7 = 10P8R
SW1 = SW-TC901-AA1G-A160T-6P
T1 T2 TP1-TP4 TP9-TP11 TP13 TP17-TP21 TP25 TP27 TP30-TP34 TP36-TP39 TP41 TP58 TP60 TP62 TP64-TP78 TP83-TP97 TP99-TP101 TP104 TP105 TP109 TP110 TP113 TP114 TP117 TP120-TP122 TP124-TP126 TP128 TP129 TP131 TP132 TP134-TP139 TP141 TP142 TP144-TP176 = TP2650
TP5 TP8 TP102 = TP2050
TP6 TP7 TP12 TP14-TP16 TP22-TP24 TP26 TP28 TP29 TP35 TP40 TP42-TP57 TP59 TP61 TP63 TP79-TP82 TP98 TP103 TP106-TP108 TP111 TP112 TP115 TP116 TP118 TP119 TP123 TP127 TP130 TP133 TP140 TP143 TP177-TP181 = TP2675
U1 = MSOP8-4_9-65
U2 = SOT23-2_8-95-6P
U3 U12 = SOT353-1-2_125-65-5P
U5 = SOT353-2_1-65-5P-1_1H
U6 U23 = SLP10-2_5X1-5-10P
U7 = QFN32-4X4-4-33P-0_9H
U8 U18 U20-U22 U25 U28 = SSOP5-P-A-TOSHIBA-B
U11 = TSSOP28-6_4-65-SLB9635TT
U13 = LQFP128-16X16-4-1_6H
U15 = QFN48-6X6-4-49P-ALC280
U16 = SENSOR-3X3-5-16P-SMT
U17 = MIC-MP45DT02TR-6P
U19 = BGA595-NVIDIA-N13P-GV2-S-A2
U24 = BGA695-INTEL-LYNX-POINT
U27 = PZ94726-3641-41H-SOCKET
U29 = TRF-9_4-1_27-24P
U30 = SOIC8-7_9-1_27
U31 U33 = SOT23-5
U32 = QFN24-4X4-5-25P-1H
VRAM1-VRAM4 = FBGA96-AMD-23EY4187MA11
Y1 Y3 = XTL-3_2X2_5-2_2X1_7
Y2 = XTL-3_2X2_5-2_2X1_6
Y4 = XTL-3_2X1_5-2_5-0_8H

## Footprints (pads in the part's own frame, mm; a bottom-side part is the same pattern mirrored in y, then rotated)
8P4R
  rect 0.406x1.092 smd: 1(-1.194,-0.8) 2(-1.194,0.8) 3(-0.406,-0.8) 4(-0.406,0.8) 5(0.406,-0.8) 6(0.406,0.8) 7(1.194,-0.8) 8(1.194,0.8)
10P8R
  rect 0.305x1.092 smd: 1(-1.27,-0.85) 2(-0.635,-0.85) 3(0,-0.85) 4(0.635,-0.85) 5(1.27,-0.85) 6(1.27,0.85) 7(0.635,0.85) 8(0,0.85) 9(-0.635,0.85) 10(-1.27,0.85)
20288-04XX-4P-L
  round 1.295 hole 0.889: 1(-3.75,0) 2(-1.25,0) 3(1.25,0) 4(3.75,0)
50273-0040L-001-4P-L
  rect 0.787x1.6 smd: 1(-1.875,2.9) 2(-0.625,2.9) 3(0.625,2.9) 4(1.875,2.9)
  rect 2.108x2.997 smd: 5(-4.425,0) 6(4.425,0)
50501-02401-001-24P-L
  rect 0.305x1.295 smd: 1(-5.75,2.8) 2(-5.25,2.8) 3(-4.75,2.8) 4(-4.25,2.8) 5(-3.75,2.8) 6(-3.25,2.8) 7(-2.75,2.8) 8(-2.25,2.8) 9(-1.75,2.8) 10(-1.25,2.8) 11(-0.75,2.8) 12(-0.25,2.8) 13(0.25,2.8) 14(0.75,2.8) 15(1.25,2.8) 16(1.75,2.8) 17(2.25,2.8) 18(2.75,2.8) 19(3.25,2.8) 20(3.75,2.8) 21(4.25,2.8) 22(4.75,2.8) 23(5.25,2.8) 24(5.75,2.8)
  rect 1.803x1.397 smd: 25(-7.4,0) 26(7.4,0)
50503-0040N-V01-4P-L
  rect 0.508x1.295 smd: 1(-1.5,2.8) 2(-0.5,2.8) 3(0.5,2.8) 4(1.5,2.8)
  rect 1.803x1.397 smd: 5(-3.65,0) 6(3.65,0)
51553-01041-001-10P-L
  rect 0.305x0.838 smd: 1(-2.25,3.175) 2(-1.75,3.175) 3(-1.25,3.175) 4(-0.75,3.175) 5(-0.25,3.175) 6(0.25,3.175) 7(0.75,3.175) 8(1.25,3.175) 9(1.75,3.175) 10(2.25,3.175)
  rect 0.787x2.007 smd: 11(-3.95,0) 12(3.95,0)
88502-260N-26P-L-SMT
  rect 0.61x1.702 smd: 1(-12.5,2.85) 2(-11.5,2.85) 3(-10.5,2.85) 4(-9.5,2.85) 5(-8.5,2.85) 6(-7.5,2.85) 7(-6.5,2.85) 8(-5.5,2.85) 9(-4.5,2.85) 10(-3.5,2.85) 11(-2.5,2.85) 12(-1.5,2.85) 13(-0.5,2.85) 14(0.5,2.85) 15(1.5,2.85) 16(2.5,2.85) 17(3.5,2.85) 18(4.5,2.85) 19(5.5,2.85) 20(6.5,2.85) 21(7.5,2.85) 22(8.5,2.85) 23(9.5,2.85) 24(10.5,2.85) 25(11.5,2.85) 26(12.5,2.85)
  rect 1.803x1.397 smd: 27(-14.65,0) 28(14.65,0)
196297-06021-3-6P-L
  rect 0.61x0.991 smd: 1(-2.5,3.47) 2(-1.5,3.47) 3(-0.5,3.47) 4(0.5,3.47) 5(1.5,3.47) 6(2.5,3.47)
  rect 0.991x1.397 smd: 7(-5.1,0) 8(5.1,0)
196479-06041-3-6P-L
  rect 0.305x0.889 smd: 1(-1.25,2.7) 2(-0.75,2.7) 3(-0.25,2.7) 4(0.25,2.7) 5(0.75,2.7) 6(1.25,2.7)
  rect 1.092x1.803 smd: 7(-3.4,0) 8(3.4,0)
AUDIO-313301-1-6P
  oval 0.991x1.905 hole 0.61x1.499: 1(-4.8,7.25) 2(4.7,1.75) 3(-4.8,-0.55) 4(4.7,-1.15) 5(4.7,7.25) 6(4.7,4.5) 7(-4.8,3.15)
BAT-C144PL-K08A9-L-8P-L
  round 1.6 hole 0.991: 1(-7,0) 2(-5,0) 3(-3,0) 4(-1,0) 5(1,0) 6(3,0) 7(5,0) 8(7,0)
  oval 1.6x3.302 hole 0.991x2.692: 9(-10.125,0) 10(10.125,0)
BGA595-NVIDIA-N13P-GV2-S-A2
  round 0.381 smd: A2(-9.9,10.7) A3(-9.1,10.7) A4(-8.3,10.7) A6(-6.6,10.7) A7(-5.8,10.7) A9(-4.12,10.7) A10(-3.32,10.7) A12(-1.64,10.7) A13(-0.84,10.7) A15(0.84,10.7) A16(1.64,10.7) A18(3.32,10.7) A19(4.12,10.7) A21(5.8,10.7) A22(6.6,10.7) A24(8.3,10.7) A25(9.1,10.7) A26(9.9,10.7) AA1(-10.7,-5.8) AA2(-9.9,-5.8) AA3(-9.1,-5.8) AA4(-8.3,-5.8) AA5(-7.5,-5.8) AA6(-6.66,-5.8) AA7(-5.8,-5.8) AA8(-4.96,-5.8) AA9(-4.12,-5.86) AA10(-3.32,-5.86) AA12(-1.64,-5.86) AA13(-0.84,-5.86) AA14(0,-5.86) AA15(0.84,-5.86) AA16(1.64,-5.86) AA18(3.32,-5.86) AA19(4.12,-5.86) AA20(4.96,-5.8) AA21(5.8,-5.8) AA22(6.66,-5.8) AA23(7.5,-5.8) AA24(8.3,-5.8) AA25(9.1,-5.8) AA26(9.9,-5.8) AA27(10.7,-5.8) AB1(-10.7,-6.6) AB2(-9.9,-6.6) AB3(-9.1,-6.6) AB4(-8.3,-6.6) AB5(-7.5,-6.6) AB6(-6.6,-6.6) AB7(-5.8,-6.66) AB8(-4.96,-6.66) AB9(-4.12,-6.66) AB10(-3.32,-6.66) AB11(-2.48,-6.66) AB12(-1.64,-6.66) AB13(-0.84,-6.66) AB14(0,-6.66) AB15(0.84,-6.66) AB16(1.64,-6.66) AB17(2.48,-6.66) AB18(3.32,-6.66) AB19(4.12,-6.66) AB20(4.96,-6.66) AB21(5.8,-6.66) AB22(6.6,-6.6) AB23(7.5,-6.6) AB24(8.3,-6.6) AB25(9.1,-6.6) AB26(9.9,-6.6) AB27(10.7,-6.6) AC2(-9.9,-7.45) AC3(-9.1,-7.45) AC4(-8.3,-7.45) AC5(-7.45,-7.45) AC6(-6.6,-7.5) AC7(-5.8,-7.5) AC8(-4.96,-7.5) AC9(-4.12,-7.5) AC10(-3.32,-7.5) AC11(-2.48,-7.5) AC12(-1.64,-7.5) AC13(-0.84,-7.5) AC14(0,-7.5) AC15(0.84,-7.5) AC16(1.64,-7.5) AC17(2.48,-7.5) AC18(3.32,-7.5) AC19(4.12,-7.5) AC20(4.96,-7.5) AC21(5.8,-7.5) AC22(6.6,-7.5) AC23(7.45,-7.45) AC24(8.3,-7.45) AC25(9.1,-7.45) AC26(9.9,-7.45) AD1(-10.7,-8.3) AD2(-9.9,-8.3) AD3(-9.1,-8.3) AD4(-8.3,-8.3) AD5(-7.45,-8.3) AD6(-6.6,-8.3) AD7(-5.8,-8.3) AD8(-4.96,-8.3) AD9(-4.12,-8.3) AD10(-3.32,-8.3) AD11(-2.48,-8.3) AD12(-1.64,-8.3) AD13(-0.84,-8.3) AD14(0,-8.3) AD15(0.84,-8.3) AD16(1.64,-8.3) AD17(2.48,-8.3) AD18(3.32,-8.3) AD19(4.12,-8.3) AD20(4.96,-8.3) AD21(5.8,-8.3) AD22(6.6,-8.3) AD23(7.45,-8.3) AD24(8.3,-8.3) AD25(9.1,-8.3) AD26(9.9,-8.3) AD27(10.7,-8.3) AE1(-10.7,-9.1) AE2(-9.9,-9.1) AE3(-9.1,-9.1) AE4(-8.3,-9.1) AE5(-7.45,-9.1) AE6(-6.6,-9.1) AE7(-5.8,-9.1) AE8(-4.96,-9.1) AE9(-4.12,-9.1) AE10(-3.32,-9.1) AE11(-2.48,-9.1) AE12(-1.64,-9.1) AE13(-0.84,-9.1) AE14(0,-9.1) AE15(0.84,-9.1) AE16(1.64,-9.1) AE17(2.48,-9.1) AE18(3.32,-9.1) AE19(4.12,-9.1) AE20(4.96,-9.1) AE21(5.8,-9.1) AE22(6.6,-9.1) AE23(7.45,-9.1) AE24(8.3,-9.1) AE25(9.1,-9.1) AE26(9.9,-9.1) AE27(10.7,-9.1) AF1(-10.7,-9.9) AF2(-9.9,-9.9) AF3(-9.1,-9.9) AF4(-8.3,-9.9) AF5(-7.45,-9.9) AF6(-6.6,-9.9) AF7(-5.8,-9.9) AF8(-4.96,-9.9) AF9(-4.12,-9.9) AF10(-3.32,-9.9) AF11(-2.48,-9.9) AF12(-1.64,-9.9) AF13(-0.84,-9.9) AF14(0,-9.9) AF15(0.84,-9.9) AF16(1.64,-9.9) AF17(2.48,-9.9) AF18(3.32,-9.9) AF19(4.12,-9.9) AF20(4.96,-9.9) AF21(5.8,-9.9) AF22(6.6,-9.9) AF23(7.45,-9.9) AF24(8.3,-9.9) AF25(9.1,-9.9) AF26(9.9,-9.9) AF27(10.7,-9.9) AG2(-9.9,-10.7) AG3(-9.1,-10.7) AG4(-8.3,-10.7) AG6(-6.6,-10.7) AG7(-5.8,-10.7) AG9(-4.12,-10.7) AG10(-3.32,-10.7) AG12(-1.64,-10.7) AG13(-0.84,-10.7) AG15(0.84,-10.7) AG16(1.64,-10.7) AG18(3.32,-10.7) AG19(4.12,-10.7) AG21(5.8,-10.7) AG22(6.6,-10.7) AG24(8.3,-10.7) AG25(9.1,-10.7) AG26(9.9,-10.7) B1(-10.7,9.9) B2(-9.9,9.9) B3(-9.1,9.9) B4(-8.3,9.9) B5(-7.45,9.9) B6(-6.6,9.9) B7(-5.8,9.9) B8(-4.96,9.9) B9(-4.12,9.9) B10(-3.32,9.9) B11(-2.48,9.9) B12(-1.64,9.9) B13(-0.84,9.9) B14(0,9.9) B15(0.84,9.9) B16(1.64,9.9) B17(2.48,9.9) B18(3.32,9.9) B19(4.12,9.9) B20(4.96,9.9) B21(5.8,9.9) B22(6.6,9.9) B23(7.45,9.9) B24(8.3,9.9) B25(9.1,9.9) B26(9.9,9.9) B27(10.7,9.9) C1(-10.7,9.1) C2(-9.9,9.1) C3(-9.1,9.1) C4(-8.3,9.1) C5(-7.45,9.1) C6(-6.6,9.1) C7(-5.8,9.1) C8(-4.96,9.1) C9(-4.12,9.1) C10(-3.32,9.1) C11(-2.48,9.1) C12(-1.64,9.1) C13(-0.84,9.1) C14(0,9.1) C15(0.84,9.1) C16(1.64,9.1) C17(2.48,9.1) C18(3.32,9.1) C19(4.12,9.1) C20(4.96,9.1) C21(5.8,9.1) C22(6.6,9.1) C23(7.45,9.1) C24(8.3,9.1) C25(9.1,9.1) C26(9.9,9.1) C27(10.7,9.1) D1(-10.7,8.3) D2(-9.9,8.3) D3(-9.1,8.3) D4(-8.3,8.3) D5(-7.45,8.3) D6(-6.6,8.3) D7(-5.8,8.3) D8(-4.96,8.3) D9(-4.12,8.3) D10(-3.32,8.3) D11(-2.48,8.3) D12(-1.64,8.3) D13(-0.84,8.3) D14(0,8.3) D15(0.84,8.3) D16(1.64,8.3) D17(2.48,8.3) D18(3.32,8.3) D19(4.12,8.3) D20(4.96,8.3) D21(5.8,8.3) D22(6.6,8.3) D23(7.45,8.3) D24(8.3,8.3) D25(9.1,8.3) D26(9.9,8.3) D27(10.7,8.3) E2(-9.9,7.45) E3(-9.1,7.45) E4(-8.3,7.45) E5(-7.45,7.45) E6(-6.6,7.5) E7(-5.8,7.5) E8(-4.96,7.5) E9(-4.12,7.5) E10(-3.32,7.5) E11(-2.48,7.5) E12(-1.64,7.5) E13(-0.84,7.5) E14(0,7.5) E15(0.84,7.5) E16(1.64,7.5) E17(2.48,7.5) E18(3.32,7.5) E19(4.12,7.5) E20(4.96,7.5) E21(5.8,7.5) E22(6.6,7.5) E23(7.45,7.45) E24(8.3,7.45) E25(9.1,7.45) E26(9.9,7.45) F1(-10.7,6.6) F2(-9.9,6.6) F3(-9.1,6.6) F4(-8.3,6.6) F5(-7.5,6.6) F6(-6.6,6.6) F7(-5.8,6.66) F8(-4.96,6.66) F9(-4.12,6.66) F10(-3.32,6.66) F11(-2.48,6.66) F12(-1.64,6.66) F13(-0.84,6.66) F14(0,6.66) F15(0.84,6.66) F16(1.64,6.66) F17(2.48,6.66) F18(3.32,6.66) F19(4.12,6.66) F20(4.96,6.66) F21(5.8,6.66) F22(6.6,6.6) F23(7.5,6.6) F24(8.3,6.6) F25(9.1,6.6) F26(9.9,6.6) F27(10.7,6.6) G1(-10.7,5.8) G2(-9.9,5.8) G3(-9.1,5.8) G4(-8.3,5.8) G5(-7.5,5.8) G6(-6.66,5.8) G7(-5.8,5.8) G8(-4.96,5.8) G9(-4.12,5.86) G10(-3.32,5.86) G12(-1.64,5.86) G13(-0.84,5.86) G14(0,5.86) G15(0.84,5.86) G16(1.64,5.86) G18(3.32,5.86) G19(4.12,5.86) G20(4.96,5.8) G21(5.8,5.8) G22(6.66,5.8) G23(7.5,5.8) G24(8.3,5.8) G25(9.1,5.8) G26(9.9,5.8) G27(10.7,5.8) H2(-9.9,4.96) H3(-9.1,4.96) H4(-8.3,4.96) H5(-7.5,4.96) H6(-6.66,4.96) H22(6.66,4.96) H23(7.5,4.96) H24(8.3,4.96) H25(9.1,4.96) H26(9.9,4.96) J1(-10.7,4.12) J2(-9.9,4.12) J3(-9.1,4.12) J4(-8.3,4.12) J5(-7.5,4.12) J6(-6.66,4.12) J7(-5.86,4.12) J21(5.86,4.12) J22(6.66,4.12) J23(7.5,4.12) J24(8.3,4.12) J25(9.1,4.12) J26(9.9,4.12) J27(10.7,4.12) K1(-10.7,3.32) K2(-9.9,3.32) K3(-9.1,3.32) K4(-8.3,3.32) K5(-7.5,3.32) K6(-6.66,3.32) K7(-5.86,3.32) K21(5.86,3.32) K22(6.66,3.32) K23(7.5,3.32) K24(8.3,3.32) K25(9.1,3.32) K26(9.9,3.32) K27(10.7,3.32) L2(-9.9,2.48) L3(-9.1,2.48) L4(-8.3,2.48) L5(-7.5,2.48) L6(-6.66,2.48) L22(6.66,2.48) L23(7.5,2.48) L24(8.3,2.48) L25(9.1,2.48) L26(9.9,2.48) M1(-10.7,1.64) M2(-9.9,1.64) M3(-9.1,1.64) M4(-8.3,1.64) M5(-7.5,1.64) M6(-6.66,1.64) M7(-5.86,1.64) M21(5.86,1.64) M22(6.66,1.64) M23(7.5,1.64) M24(8.3,1.64) M25(9.1,1.64) M26(9.9,1.64) M27(10.7,1.64) N1(-10.7,0.84) N2(-9.9,0.84) N3(-9.1,0.84) N4(-8.3,0.84) N5(-7.5,0.84) N6(-6.66,0.84) N7(-5.86,0.84) N21(5.86,0.84) N22(6.66,0.84) N23(7.5,0.84) N24(8.3,0.84) N25(9.1,0.84) N26(9.9,0.84) N27(10.7,0.84) P2(-9.9,0) P3(-9.1,0) P4(-8.3,0) P5(-7.5,0) P6(-6.66,0) P22(6.66,0) P23(7.5,0) P24(8.3,0) P25(9.1,0) P26(9.9,0) R1(-10.7,-0.84) R2(-9.9,-0.84) R3(-9.1,-0.84) R4(-8.3,-0.84) R5(-7.5,-0.84) R6(-6.66,-0.84) R7(-5.86,-0.84) R21(5.86,-0.84) R22(6.66,-0.84) R23(7.5,-0.84) R24(8.3,-0.84) R25(9.1,-0.84) R26(9.9,-0.84) R27(10.7,-0.84) T1(-10.7,-1.64) T2(-9.9,-1.64) T3(-9.1,-1.64) T4(-8.3,-1.64) T5(-7.5,-1.64) T6(-6.66,-1.64) T7(-5.86,-1.64) T21(5.86,-1.64) T22(6.66,-1.64) T23(7.5,-1.64) T24(8.3,-1.64) T25(9.1,-1.64) T26(9.9,-1.64) T27(10.7,-1.64) U2(-9.9,-2.48) U3(-9.1,-2.48) U4(-8.3,-2.48) U5(-7.5,-2.48) U6(-6.66,-2.48) U22(6.66,-2.48) U23(7.5,-2.48) U24(8.3,-2.48) U25(9.1,-2.48) U26(9.9,-2.48) V1(-10.7,-3.32) V2(-9.9,-3.32) V3(-9.1,-3.32) V4(-8.3,-3.32) V5(-7.5,-3.32) V6(-6.66,-3.32) V7(-5.86,-3.32) V21(5.86,-3.32) V22(6.66,-3.32) V23(7.5,-3.32) V24(8.3,-3.32) V25(9.1,-3.32) V26(9.9,-3.32) V27(10.7,-3.32) W1(-10.7,-4.12) W2(-9.9,-4.12) W3(-9.1,-4.12) W4(-8.3,-4.12) W5(-7.5,-4.12) W6(-6.66,-4.12) W7(-5.86,-4.12) W21(5.86,-4.12) W22(6.66,-4.12) W23(7.5,-4.12) W24(8.3,-4.12) W25(9.1,-4.12) W26(9.9,-4.12) W27(10.7,-4.12) Y2(-9.9,-4.96) Y3(-9.1,-4.96) Y4(-8.3,-4.96) Y5(-7.5,-4.96) Y6(-6.66,-4.96) Y22(6.66,-4.96) Y23(7.5,-4.96) Y24(8.3,-4.96) Y25(9.1,-4.96) Y26(9.9,-4.96)
  round 0.4 smd: K10(-4,4) K11(-3,4) K12(-2,4) K13(-1,4) K14(0,4) K15(1,4) K16(2,4) K17(3,4) K18(4,4) L10(-4,3) L11(-3,3) L12(-2,3) L13(-1,3) L14(0,3) L15(1,3) L16(2,3) L17(3,3) L18(4,3) M10(-4,2) M11(-3,2) M12(-2,2) M13(-1,2) M14(0,2) M15(1,2) M16(2,2) M17(3,2) M18(4,2) N10(-4,1) N11(-3,1) N12(-2,1) N13(-1,1) N14(0,1) N15(1,1) N16(2,1) N17(3,1) N18(4,1) P10(-4,0) P11(-3,0) P12(-2,0) P13(-1,0) P14(0,0) P15(1,0) P16(2,0) P17(3,0) P18(4,0) R10(-4,-1) R11(-3,-1) R12(-2,-1) R13(-1,-1) R14(0,-1) R15(1,-1) R16(2,-1) R17(3,-1) R18(4,-1) T10(-4,-2) T11(-3,-2) T12(-2,-2) T13(-1,-2) T14(0,-2) T15(1,-2) T16(2,-2) T17(3,-2) T18(4,-2) U10(-4,-3) U11(-3,-3) U12(-2,-3) U13(-1,-3) U14(0,-3) U15(1,-3) U16(2,-3) U17(3,-3) U18(4,-3) V10(-4,-4) V11(-3,-4) V12(-2,-4) V13(-1,-4) V14(0,-4) V15(1,-4) V16(2,-4) V17(3,-4) V18(4,-4)
BGA695-INTEL-LYNX-POINT
  round 0.483 smd: A2(8.689,-9.312) A44(-8.788,-9.312) B1(9.312,-8.689) B45(-9.312,-8.788) BD1(9.312,8.788) BD45(-9.312,8.788) BE2(8.788,9.312) BE44(-8.788,9.312)
  round 0.356 smd: A4(8.096,-9.312) A5(7.503,-9.312) A41(-7.602,-9.312) A43(-8.195,-9.312) B2(8.709,-8.709) B44(-8.709,-8.709) BA1(9.312,7.602) BA45(-9.312,7.602) BC1(9.312,8.195) BC45(-9.312,8.195) BD2(8.709,8.709) BD44(-8.709,8.709) BE3(8.195,9.312) BE5(7.602,9.312) BE41(-7.602,9.312) BE43(-8.195,9.312) C45(-9.312,-8.195) D1(9.312,-8.096) E1(9.312,-7.503) E45(-9.312,-7.602)
  round 0.33 smd: A6(6.83,-9.312) A40(-6.929,-9.312) AY1(9.312,6.929) AY45(-9.312,6.929) B4(7.997,-8.726) B42(-7.921,-8.675) BA2(8.762,7.352) BB2(8.749,7.997) BB44(-8.675,7.921) BD4(7.921,8.675) BD41(-7.352,8.762) BD42(-7.997,8.749) BE6(6.929,9.312) BE40(-6.929,9.312) D2(8.675,-7.921) D44(-8.749,-7.997) E44(-8.762,-7.352) F1(9.312,-6.83) F45(-9.312,-6.929)
  round 0.305 smd: A8(6.096,-9.312) A10(5.283,-9.312) A12(4.47,-9.312) A14(3.658,-9.312) A16(2.845,-9.312) A18(2.032,-9.312) A20(1.219,-9.312) A22(0.406,-9.312) A24(-0.406,-9.312) A26(-1.219,-9.312) A28(-2.032,-9.312) A30(-2.845,-9.312) A32(-3.658,-9.312) A34(-4.47,-9.312) A36(-5.283,-9.312) A38(-6.096,-9.312) AA2(8.86,-0.835) AA4(7.976,-0.813) AA14(3.797,-0.485) AA16(2.985,-0.485) AA18(2.172,-0.485) AA20(1.359,-0.485) AA22(0.546,-0.485) AA24(-0.267,-0.485) AA26(-1.079,-0.485) AA28(-1.892,-0.485) AA30(-2.705,-0.485) AA32(-3.518,-0.485) AA42(-7.976,-0.813) AA44(-8.86,-0.791) AB1(9.312,-0.406) AB3(8.408,-0.406) AB6(7.379,-0.305) AB7(6.782,-0.305) AB8(6.185,-0.305) AB10(5.588,-0.305) AB11(4.991,-0.305) AB12(4.394,-0.305) AB34(-4.394,-0.305) AB35(-4.991,-0.305) AB36(-5.588,-0.305) AB38(-6.185,-0.305) AB39(-6.782,-0.305) AB40(-7.379,-0.305) AB43(-8.408,-0.406) AB45(-9.312,-0.406) AC2(8.84,0) AC44(-8.84,0) AD1(9.312,0.406) AD3(8.408,0.406) AD6(7.379,0.305) AD7(6.782,0.305) AD8(6.185,0.305) AD10(5.588,0.305) AD11(4.991,0.305) AD12(4.394,0.305) AD14(3.797,0.175) AD16(2.985,0.175) AD18(2.172,0.175) AD20(1.359,0.175) AD22(0.546,0.175) AD24(-0.267,0.175) AD26(-1.079,0.175) AD28(-1.892,0.175) AD30(-2.705,0.175) AD32(-3.518,0.175) AD34(-4.394,0.305) AD35(-4.991,0.305) AD36(-5.588,0.305) AD38(-6.185,0.305) AD39(-6.782,0.305) AD40(-7.379,0.305) AD43(-8.408,0.406) AD45(-9.312,0.406) AE2(8.86,0.791) AE4(7.976,0.813) AE14(3.797,0.836) AE16(2.985,0.836) AE18(2.172,0.836) AE20(1.359,0.836) AE22(0.546,0.836) AE24(-0.267,0.836) AE26(-1.079,0.836) AE28(-1.892,0.836) AE30(-2.705,0.836) AE32(-3.518,0.836) AE42(-7.976,0.813) AE44(-8.86,0.835) AF1(9.312,1.219) AF3(8.408,1.219) AF6(7.379,1.283) AF7(6.782,1.283) AF8(6.185,1.283) AF10(5.588,1.283) AF11(4.991,1.283) AF12(4.394,1.283) AF34(-4.394,1.283) AF35(-4.991,1.283) AF36(-5.588,1.283) AF38(-6.185,1.283) AF39(-6.782,1.283) AF40(-7.379,1.283) AF43(-8.408,1.219) AF45(-9.312,1.219) AG2(8.84,1.626) AG14(3.797,1.496) AG16(2.985,1.496) AG18(2.172,1.496) AG20(1.359,1.496) AG22(0.546,1.496) AG24(-0.267,1.496) AG26(-1.079,1.496) AG28(-1.892,1.496) AG30(-2.705,1.496) AG32(-3.518,1.496) AG44(-8.84,1.626) AH1(9.312,2.032) AH3(8.408,2.032) AH43(-8.408,2.032) AH45(-9.312,2.032) AJ2(8.86,2.417) AJ4(7.976,2.438) AJ6(7.379,2.261) AJ7(6.782,2.261) AJ8(6.185,2.261) AJ10(5.588,2.261) AJ11(4.991,2.261) AJ12(4.394,2.261) AJ14(3.797,2.156) AJ16(2.985,2.156) AJ18(2.172,2.156) AJ20(1.359,2.156) AJ22(0.546,2.156) AJ24(-0.267,2.156) AJ26(-1.079,2.156) AJ28(-1.892,2.156) AJ30(-2.705,2.156) AJ32(-3.518,2.156) AJ34(-4.394,2.261) AJ35(-4.991,2.261) AJ36(-5.588,2.261) AJ38(-6.185,2.261) AJ39(-6.782,2.261) AJ40(-7.379,2.261) AJ42(-7.976,2.438) AJ44(-8.86,2.46) AK1(9.312,2.845) AK3(8.408,2.845) AK14(3.797,2.817) AK16(2.985,2.817) AK18(2.172,2.817) AK20(1.359,2.817) AK22(0.546,2.817) AK24(-0.267,2.817) AK26(-1.079,2.817) AK28(-1.892,2.817) AK30(-2.705,2.817) AK32(-3.518,2.817) AK43(-8.408,2.845) AK45(-9.312,2.845) AL2(8.84,3.251) AL6(7.379,3.239) AL7(6.782,3.239) AL8(6.185,3.239) AL10(5.588,3.239) AL11(4.991,3.239) AL12(4.394,3.239) AL34(-4.394,3.239) AL35(-4.991,3.239) AL36(-5.588,3.239) AL38(-6.185,3.239) AL39(-6.782,3.239) AL40(-7.379,3.239) AL44(-8.84,3.251) AM1(9.312,3.658) AM3(8.408,3.658) AM14(3.797,3.477) AM16(2.985,3.477) AM18(2.172,3.477) AM20(1.359,3.477) AM22(0.546,3.477) AM24(-0.267,3.477) AM26(-1.079,3.477) AM28(-1.892,3.477) AM30(-2.705,3.477) AM32(-3.518,3.477) AM43(-8.408,3.658) AM45(-9.312,3.658) AN2(8.86,4.042) AN4(7.976,4.064) AN6(7.379,4.216) AN7(6.782,4.216) AN8(6.185,4.216) AN10(5.588,4.216) AN11(4.991,4.216) AN34(-4.343,4.216) AN35(-4.991,4.216) AN36(-5.588,4.216) AN38(-6.185,4.216) AN39(-6.782,4.216) AN40(-7.379,4.216) AN42(-7.976,4.064) AN44(-8.86,4.086) AP1(9.312,4.47) AP3(8.408,4.47) AP13(4.216,4.343) AP15(3.239,4.394) AP17(2.261,4.394) AP20(1.283,4.394) AP22(0.305,4.394) AP24(-0.305,4.394) AP26(-1.283,4.394) AP29(-2.261,4.394) AP31(-3.239,4.394) AP43(-8.408,4.47) AP45(-9.312,4.47) AR2(8.84,4.877) AR13(4.216,4.991) AR15(3.239,4.991) AR17(2.261,4.991) AR20(1.283,4.991) AR22(0.305,4.991) AR24(-0.305,4.991) AR26(-1.283,4.991) AR29(-2.261,4.991) AR31(-3.239,4.991) AR33(-4.216,4.991) AR44(-8.84,4.877) AT1(9.312,5.283) AT3(8.408,5.283) AT6(7.379,5.194) AT7(6.782,5.194) AT8(6.185,5.194) AT10(5.194,5.588) AT13(4.216,5.588) AT15(3.239,5.588) AT17(2.261,5.588) AT20(1.283,5.588) AT22(0.305,5.588) AT24(-0.305,5.588) AT26(-1.283,5.588) AT29(-2.261,5.588) AT31(-3.239,5.588) AT33(-4.216,5.588) AT36(-5.588,5.194) AT38(-6.185,5.194) AT39(-6.782,5.194) AT40(-7.379,5.194) AT43(-8.408,5.283) AT45(-9.312,5.283) AU2(8.86,5.668) AU4(7.976,5.69) AU42(-7.976,5.69) AU44(-8.86,5.711) AV1(9.312,6.096) AV3(8.408,6.096) AV6(7.379,6.172) AV7(6.782,6.172) AV10(5.194,6.185) AV13(4.216,6.185) AV15(3.239,6.185) AV17(2.261,6.185) AV20(1.283,6.185) AV22(0.305,6.185) AV24(-0.305,6.185) AV26(-1.283,6.185) AV29(-2.261,6.185) AV31(-3.239,6.185) AV33(-4.216,6.185) AV36(-5.194,6.185) AV40(-7.379,6.172) AV43(-8.408,6.096) AV45(-9.312,6.096) AW2(8.84,6.502) AW8(6.172,6.782) AW10(5.194,6.782) AW13(4.216,6.782) AW15(3.239,6.782) AW17(2.261,6.782) AW20(1.283,6.782) AW22(0.305,6.782) AW24(-0.305,6.782) AW26(-1.283,6.782) AW29(-2.261,6.782) AW31(-3.239,6.782) AW33(-4.216,6.782) AW36(-5.194,6.782) AW38(-6.172,6.782) AW40(-7.811,6.909) AW44(-8.84,6.502) AY3(8.335,6.909) AY5(7.569,6.739) AY7(6.909,7.811) AY8(6.172,7.379) AY10(5.194,7.379) AY13(4.216,7.379) AY15(3.239,7.379) AY17(2.261,7.379) AY20(1.283,7.379) AY22(0.305,7.379) AY24(-0.305,7.379) AY26(-1.283,7.379) AY29(-2.261,7.379) AY31(-3.239,7.379) AY33(-4.216,7.379) AY36(-5.194,7.379) AY38(-6.172,7.379) AY43(-8.408,6.909) B5(7.352,-8.726) B7(6.574,-8.76) B9(5.668,-8.86) B11(4.877,-8.84) B13(4.042,-8.86) B15(3.251,-8.84) B17(2.417,-8.86) B19(1.626,-8.84) B21(0.791,-8.86) B23(0,-8.84) B25(-0.835,-8.86) B27(-1.626,-8.84) B29(-2.46,-8.86) B31(-3.251,-8.84) B33(-4.086,-8.86) B35(-4.877,-8.84) B37(-5.711,-8.86) B39(-6.502,-8.84) BA40(-6.739,7.569) BB4(7.921,7.99) BB9(5.69,7.976) BB13(4.064,7.976) BB17(2.438,7.976) BB21(0.813,7.976) BB25(-0.813,7.976) BB29(-2.438,7.976) BB33(-4.064,7.976) BB37(-5.69,7.976) BB42(-7.99,7.921) BC6(6.909,8.408) BC8(6.096,8.408) BC10(5.283,8.408) BC12(4.47,8.408) BC14(3.658,8.408) BC16(2.845,8.408) BC18(2.032,8.408) BC20(1.219,8.408) BC22(0.406,8.408) BC24(-0.406,8.408) BC26(-1.219,8.408) BC28(-2.032,8.408) BC30(-2.845,8.408) BC32(-3.658,8.408) BC34(-4.47,8.408) BC36(-5.283,8.408) BC38(-6.096,8.408) BC40(-6.909,8.335) BD7(6.502,8.84) BD9(5.711,8.86) BD11(4.877,8.84) BD13(4.086,8.86) BD15(3.251,8.84) BD17(2.46,8.86) BD19(1.626,8.84) BD21(0.835,8.86) BD23(0,8.84) BD25(-0.791,8.86) BD27(-1.626,8.84) BD29(-2.417,8.86) BD31(-3.251,8.84) BD33(-4.042,8.86) BD35(-4.877,8.84) BD37(-5.668,8.86) BD39(-6.502,8.84) BE8(6.096,9.312) BE10(5.283,9.312) BE12(4.47,9.312) BE14(3.658,9.312) BE16(2.845,9.312) BE18(2.032,9.312) BE20(1.219,9.312) BE22(0.406,9.312) BE24(-0.406,9.312) BE26(-1.219,9.312) BE28(-2.032,9.312) BE30(-2.845,9.312) BE32(-3.658,9.312) BE34(-4.47,9.312) BE36(-5.283,9.312) BE38(-6.096,9.312) C6(6.943,-8.295) C8(6.096,-8.408) C10(5.283,-8.408) C12(4.47,-8.408) C14(3.658,-8.408) C16(2.845,-8.408) C18(2.032,-8.408) C20(1.219,-8.408) C22(0.406,-8.408) C24(-0.406,-8.408) C26(-1.219,-8.408) C28(-2.032,-8.408) C30(-2.845,-8.408) C32(-3.658,-8.408) C34(-4.47,-8.408) C36(-5.283,-8.408) C38(-6.096,-8.408) C40(-6.909,-8.408) D4(7.99,-7.921) D9(5.69,-7.976) D13(4.064,-7.976) D17(2.438,-7.976) D21(0.813,-7.976) D25(-0.813,-7.976) D29(-2.438,-7.976) D33(-4.064,-7.976) D37(-5.69,-7.976) D42(-7.921,-7.99) E6(6.739,-7.569) F3(8.335,-6.953) F8(6.172,-7.379) F10(5.194,-7.379) F13(4.216,-7.379) F15(3.239,-7.379) F17(2.261,-7.379) F20(1.283,-7.379) F22(0.305,-7.379) F24(-0.305,-7.379) F26(-1.283,-7.379) F29(-2.261,-7.379) F31(-3.239,-7.379) F33(-4.216,-7.379) F36(-5.194,-7.379) F38(-6.172,-7.379) F39(-6.909,-7.811) F41(-7.569,-6.739) F43(-8.335,-6.909) G2(8.78,-6.561) G5(7.75,-6.833) G8(6.172,-6.782) G10(5.194,-6.782) G13(4.216,-6.782) G15(3.239,-6.782) G17(2.261,-6.782) G20(1.283,-6.782) G22(0.305,-6.782) G24(-0.305,-6.782) G26(-1.283,-6.782) G29(-2.261,-6.782) G31(-3.239,-6.782) G33(-4.216,-6.782) G36(-5.194,-6.782) G38(-6.172,-6.782) G44(-8.84,-6.502) H1(9.312,-6.096) H3(8.408,-6.096) H6(7.379,-6.172) H7(6.782,-6.172) H10(5.194,-6.185) H13(4.216,-6.185) H15(3.239,-6.185) H17(2.261,-6.185) H20(1.283,-6.185) H22(0.305,-6.185) H24(-0.305,-6.185) H26(-1.283,-6.185) H29(-2.261,-6.185) H31(-3.239,-6.185) H33(-4.216,-6.185) H36(-5.194,-6.185) H39(-6.782,-6.172) H40(-7.379,-6.172) H43(-8.408,-6.096) H45(-9.312,-6.096) J2(8.86,-5.711) J4(7.976,-5.69) J42(-7.976,-5.69) J44(-8.86,-5.668) K1(9.312,-5.283) K3(8.408,-5.283) K6(7.379,-5.194) K7(6.782,-5.194) K8(6.185,-5.194) K10(5.588,-5.194) K13(4.216,-5.588) K15(3.239,-5.588) K17(2.261,-5.588) K20(1.283,-5.588) K22(0.305,-5.588) K24(-0.305,-5.588) K26(-1.283,-5.588) K29(-2.261,-5.588) K31(-3.239,-5.588) K33(-4.216,-5.588) K36(-5.194,-5.588) K38(-6.185,-5.194) K39(-6.782,-5.194) K40(-7.379,-5.194) K43(-8.408,-5.283) K45(-9.312,-5.283) L2(8.84,-4.877) L13(4.216,-4.991) L15(3.239,-4.991) L17(2.261,-4.991) L20(1.283,-4.991) L22(0.305,-4.991) L24(-0.305,-4.991) L26(-1.283,-4.991) L29(-2.261,-4.991) L31(-3.239,-4.991) L33(-4.216,-4.991) L44(-8.84,-4.877) M1(9.312,-4.47) M3(8.408,-4.47) M15(3.239,-4.394) M17(2.261,-4.394) M20(1.283,-4.394) M22(0.305,-4.394) M24(-0.305,-4.394) M26(-1.283,-4.394) M29(-2.261,-4.394) M31(-3.239,-4.394) M33(-4.216,-4.343) M43(-8.408,-4.47) M45(-9.312,-4.47) N2(8.86,-4.086) N4(7.976,-4.064) N6(7.379,-4.216) N7(6.782,-4.216) N8(6.185,-4.216) N10(5.588,-4.216) N11(4.991,-4.216) N12(4.343,-4.216) N35(-4.991,-4.216) N36(-5.588,-4.216) N38(-6.185,-4.216) N39(-6.782,-4.216) N40(-7.379,-4.216) N42(-7.976,-4.064) N44(-8.86,-4.042) P1(9.312,-3.658) P3(8.408,-3.658) P14(3.797,-3.787) P16(2.985,-3.787) P18(2.172,-3.787) P20(1.359,-3.787) P22(0.546,-3.787) P24(-0.267,-3.787) P26(-1.079,-3.787) P28(-1.892,-3.787) P30(-2.705,-3.787) P32(-3.518,-3.787) P43(-8.408,-3.658) P45(-9.312,-3.658) R2(8.84,-3.251) R6(7.379,-3.239) R7(6.782,-3.239) R8(6.185,-3.239) R10(5.588,-3.239) R11(4.991,-3.239) R12(4.394,-3.239) R14(3.797,-3.127) R16(2.985,-3.127) R18(2.172,-3.127) R20(1.359,-3.127) R22(0.546,-3.127) R24(-0.267,-3.127) R26(-1.079,-3.127) R28(-1.892,-3.127) R30(-2.705,-3.127) R32(-3.518,-3.127) R34(-4.394,-3.239) R35(-4.991,-3.239) R36(-5.588,-3.239) R38(-6.185,-3.239) R39(-6.782,-3.239) R40(-7.379,-3.239) R44(-8.84,-3.251) T1(9.312,-2.845) T3(8.408,-2.845) T43(-8.408,-2.845) T45(-9.312,-2.845) U2(8.86,-2.46) U4(7.976,-2.438) U6(7.379,-2.261) U7(6.782,-2.261) U8(6.185,-2.261) U10(5.588,-2.261) U11(4.991,-2.261) U12(4.394,-2.261) U14(3.797,-2.466) U16(2.985,-2.466) U18(2.172,-2.466) U20(1.359,-2.466) U22(0.546,-2.466) U24(-0.267,-2.466) U26(-1.079,-2.466) U28(-1.892,-2.466) U30(-2.705,-2.466) U32(-3.518,-2.466) U34(-4.394,-2.261) U35(-4.991,-2.261) U36(-5.588,-2.261) U38(-6.185,-2.261) U39(-6.782,-2.261) U40(-7.379,-2.261) U42(-7.976,-2.438) U44(-8.86,-2.417) V1(9.312,-2.032) V3(8.408,-2.032) V14(3.797,-1.806) V16(2.985,-1.806) V18(2.172,-1.806) V20(1.359,-1.806) V22(0.546,-1.806) V24(-0.267,-1.806) V26(-1.079,-1.806) V28(-1.892,-1.806) V30(-2.705,-1.806) V32(-3.518,-1.806) V43(-8.408,-2.032) V45(-9.312,-2.032) W2(8.84,-1.626) W44(-8.84,-1.626) Y1(9.312,-1.219) Y3(8.408,-1.219) Y6(7.379,-1.283) Y7(6.782,-1.283) Y8(6.185,-1.283) Y10(5.588,-1.283) Y11(4.991,-1.283) Y12(4.394,-1.283) Y14(3.797,-1.146) Y16(2.985,-1.146) Y18(2.172,-1.146) Y20(1.359,-1.146) Y22(0.546,-1.146) Y24(-0.267,-1.146) Y26(-1.079,-1.146) Y28(-1.892,-1.146) Y30(-2.705,-1.146) Y32(-3.518,-1.146) Y34(-4.394,-1.283) Y35(-4.991,-1.283) Y36(-5.588,-1.283) Y38(-6.185,-1.283) Y39(-6.782,-1.283) Y40(-7.379,-1.283) Y43(-8.408,-1.219) Y45(-9.312,-1.219)
